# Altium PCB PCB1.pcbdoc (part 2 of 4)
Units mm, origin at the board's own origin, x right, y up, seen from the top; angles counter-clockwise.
Board outline 94.87 x 122.94 mm, 4 copper layers (Top Layer, Inner1, Inner2, Bottom Layer); 129 components, 127 nets, 713 pads, 345 vias.
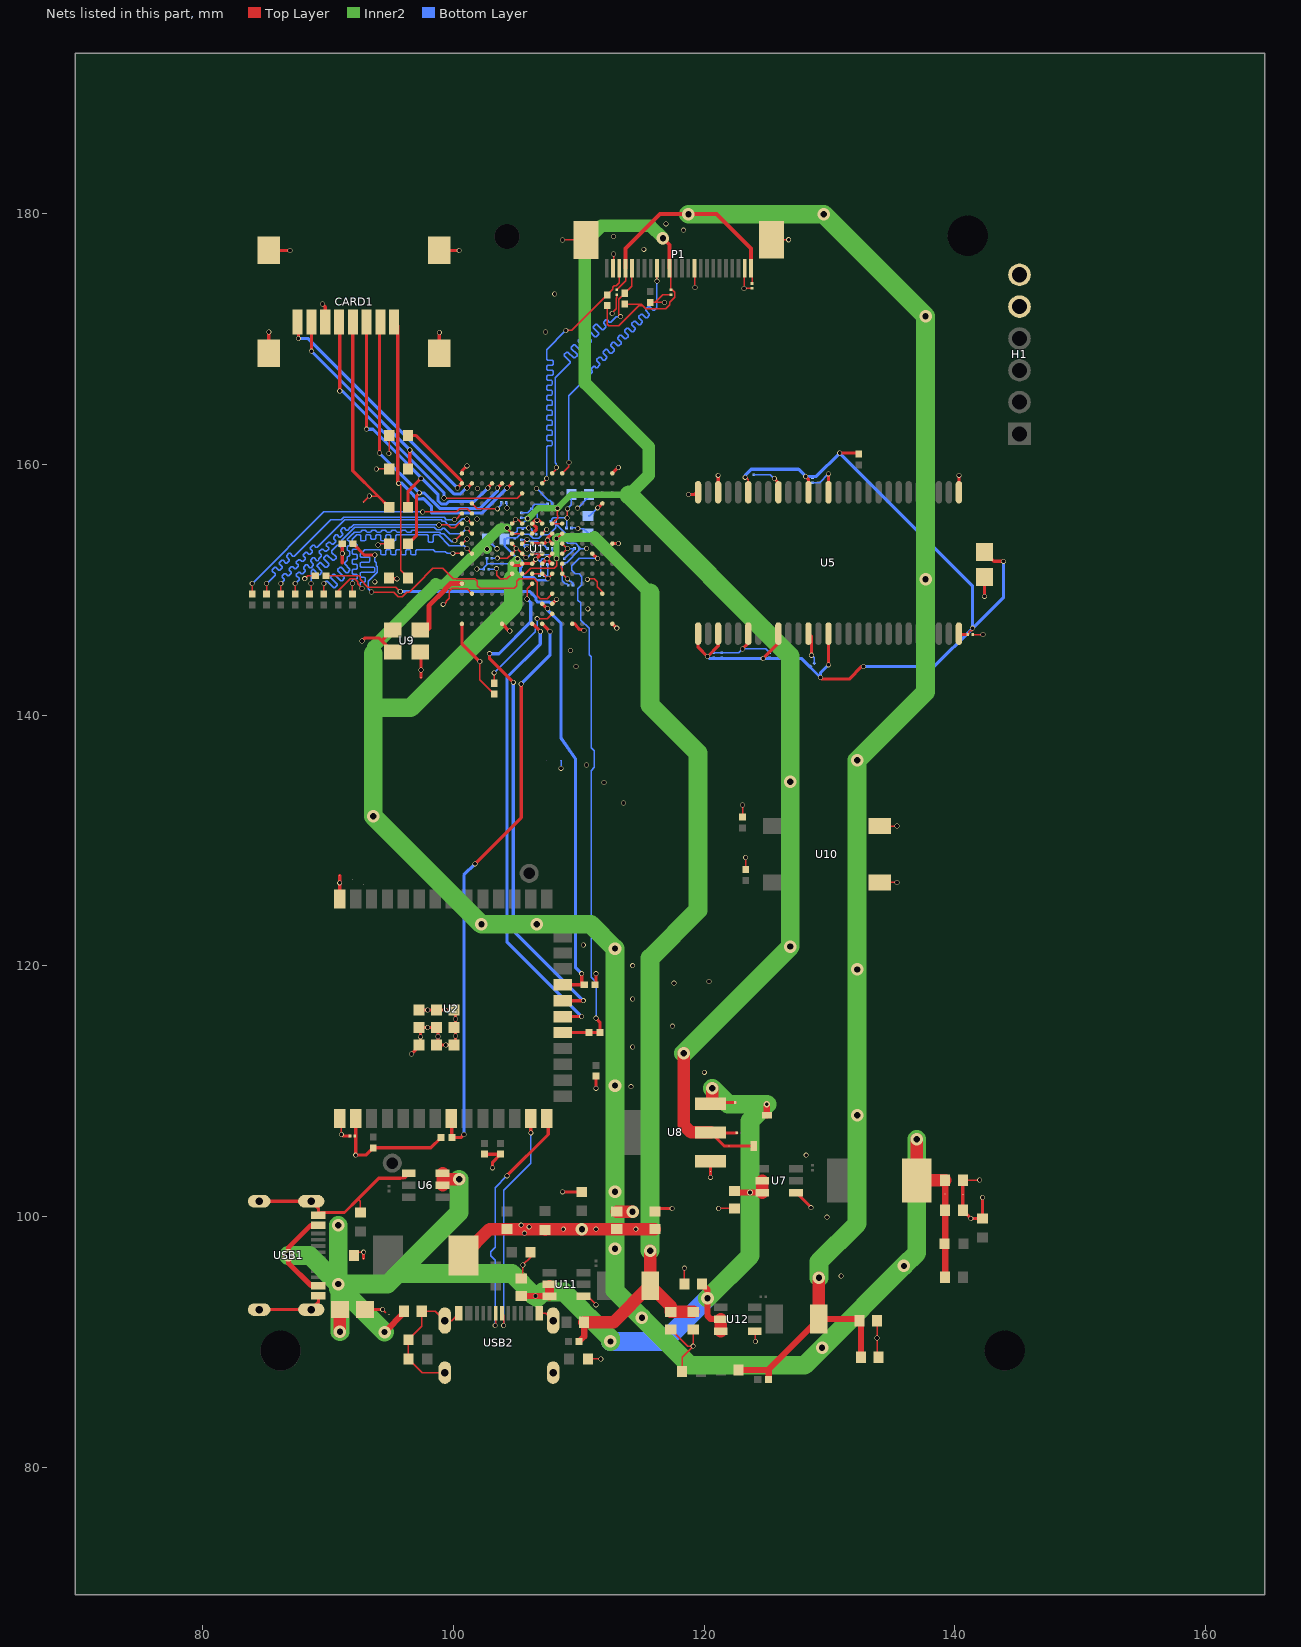
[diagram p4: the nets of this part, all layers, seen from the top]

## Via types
v1: diameter 0.4, hole 0.3, Top Layer to Bottom Layer, 308 vias
v2: diameter 1, hole 0.5, Top Layer to Bottom Layer, 35 vias
v3: diameter 0.5, hole 0.3, Top Layer to Bottom Layer, 2 vias

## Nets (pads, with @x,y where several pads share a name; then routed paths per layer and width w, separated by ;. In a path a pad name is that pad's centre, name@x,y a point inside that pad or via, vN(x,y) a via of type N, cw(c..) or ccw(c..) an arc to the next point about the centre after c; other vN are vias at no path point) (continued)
$2N5507: R23.2 U1.P10 | length 20.1
  Top Layer w0.1: R23.2@89.841,151.13 92.456,151.13 92.562,151.024 92.562,150.836 93.178,150.22 95.398,150.22 v1(95.758,149.86)
  Top Layer w0.254: U1.P10@107.88,148.889 108.204,149.213 v1@108.204,149.225
  Bottom Layer w0.254: v1(95.758,149.86) 106.11,149.86 106.589,149.381 106.589,149.159 106.73,149.018 107.676,149.018 107.776,148.918 107.897,148.918 v1(108.225,149.246)
$2N5509: R24.2 U1.N10 | length 23.9
  Top Layer w0.1: v1(93.472,149.818) 95.231,149.818 95.591,149.458 95.925,149.458 96.285,149.818 96.478,149.818 97.722,151.062 97.722,151.067 98.358,151.703 99.151,151.703 99.983,150.871 101.694,150.871 101.898,150.667 101.898,150.331 102.122,150.107 104.038,150.107 104.045,150.114 104.515,150.114 104.522,150.107 104.838,150.107 105.062,150.331 105.062,150.689 105.244,150.871 106.438,150.871 106.698,150.611 106.698,149.531 106.922,149.307 107.498,149.307 U1.N10@107.88,149.689
  Top Layer w0.254: R24.2@92,153.67 92.889,152.781 v1(93.726,152.781)
  Bottom Layer w0.1: v1(93.472,149.818) 93.218,150.072 93.218,150.697 93.926,151.405 93.926,151.829 93.853,151.902 93.853,152.146 93.726,152.273 v1(93.726,152.781)
$2N5511: R25.2 U1.R10 | length 7.9
  Top Layer w0.1: R25.2@103.251,142.546 v1(103.251,143.383) ; v1(106.68,147.701) 107.492,147.701 U1.R10@107.88,148.089
  Bottom Layer w0.1: v1(103.251,143.383) 106.532,146.664 106.532,146.852 106.68,147 v1(106.68,147.701)
+1V1: C25.2 C27.2 C28.2 C41.1 C42.1 C43.1 C44.1 C49.1 C53.1 C54.1 C61.1 L2.2 pad.55@139.233,101.796 R15.2 U1.G6 U1.G7 U1.L8 U1.L9 U1.L10 | length 172.4
  Top Layer w0.1: v1@104.267,154.94 104.267,154.902 U1.G6@104.68,154.489 U1.G7@105.48,154.489 ; U1.L8@106.28,151.289 U1.L9@107.08,151.289 107.146,151.289 v1(107.539,150.897) 107.88,151.238 U1.L10@107.88,151.289
  Top Layer w0.5: C25.2@139.233,95.162 C28.2@139.233,100.496 pad.55@139.233,101.796 C27.2@139.233,102.909
  Top Layer w1: v2(136.969,106.172) L2.2@136.969,102.864 137.014,102.909 C27.2@139.233,102.909
  Inner2 w0.7: 98.601,150.439 98.614,150.426 ; 103.835,154.932 v1(104.275,154.932)
  Inner2 w0.8: 98.601,150.439 99.936,150.439 ; 99.418,150.613 101.342,152.537 101.403,152.537 101.844,152.978 101.844,153.039 102.371,153.567 ; 99.949,150.426 99.936,150.439 ; v1(102.689,153.249) 102.371,153.567 ; 103.835,154.932 103.813,154.909 103.714,154.909 102.371,153.567 ; v1@105.039,152.302 104.728,151.99 104.728,150.859 104.308,150.439 99.936,150.439
  Inner2 w1: 93.612,145.444 96.696,148.528 96.696,148.534 98.601,150.439
  Inner2 w1.5: 93.609,144.917 93.609,140.564 ; 104.728,150.859 104.775,150.812 104.775,148.785 96.579,140.589 93.634,140.589 93.609,140.564 ; v2(136.969,106.172) 136.969,97.091 v2(135.94,96.062) v2(129.41,89.532) 128.016,88.138 118.841,88.138 v2(115.042,91.937) 112.89,94.089 v2(112.89,97.437) v2(112.89,101.976) v2(112.89,110.453) v2(112.89,121.382) 110.955,123.317 v2(106.641,123.317) v2(102.235,123.317) v2(93.609,131.943) 93.609,140.564
  Bottom Layer w0.1: C61.1@104.205,154.051 104.309,154.155 105.057,154.155 105.33,154.427 106.05,154.427 106.357,154.12 106.801,154.12 107.09,154.411 107.609,154.411 108.145,154.948 108.145,155.194 ; C53.1@107.256,151.13 107.442,151.13 107.51,151.062 C49.1@107.51,152.019 ; C43.1@108.145,155.448 108.145,155.194 ; C44.1@109.161,154.178 109.161,154.289 108.256,155.194 108.145,155.194
  Bottom Layer w0.2: C61.1@104.078,154.051 104.078,153.518 v1(105.117,152.479) 105.245,152.479 105.339,152.385 105.339,152.381 105.445,152.275 105.445,151.859 C54.1@105.351,151.765 105.351,151.316 105.664,151.003 106.422,151.003 106.676,150.749 107.525,150.749 v1@107.539,150.762
+1V8: C29.1 C32.2 C35.1 C62.1 C63.1 P1.11 pad.55@121.997,105.627 R38.2 R39.2 U1.F10 U1.F11 U8.2 | length 124.4
  Top Layer w0.1: v1(108.312,156.504) 108.312,156.262 108.298,156.247 108.298,155.931 108.312,155.917 108.312,155.721 U1.F10@107.88,155.289 U1.F11@108.68,155.289 ; R38.2@112.268,172.668 112.268,172.205 112.264,172.201 112.264,171.2 112.395,171.069 113.177,171.069 114.776,172.668 115.112,172.668 ; R39.2@113.665,172.795 114.985,172.795 115.112,172.668 ; P1.11@117.237,175.655 117.336,175.557 117.336,174.458 117.348,174.446 C35.1@117.348,173.931 ; 117.459,173.931 117.66,173.73 117.66,173.352 117.242,172.934 117.242,172.756 116.924,172.437 115.343,172.437 115.112,172.668
  Top Layer w0.254: C29.1@122.614,106.68 120.546,106.68 121.599,105.627 pad.55@121.997,105.627 C32.2@123.952,105.627
  Top Layer w0.3: v2(116.713,178.054) 117.237,177.53 P1.11@117.237,175.655
  Top Layer w1: v2(118.364,113.03) 118.364,107.315 118.97,106.709 U8.2@120.517,106.709
  Inner2 w0.5: v1(105.928,155.689) 105.965,155.689 106.781,156.504 v1(108.312,156.504) 108.491,156.683 108.491,156.713 109.353,157.575 114.014,157.575
  Inner2 w1: 114.014,157.575 115.57,159.131 115.57,161.417 110.49,166.497 110.49,177.71 111.813,179.033 115.734,179.033 v2(116.713,178.054)
  Inner2 w1.5: 114.014,157.575 126.873,144.716 v2(126.873,134.685) v2(126.873,121.539) v2(118.364,113.03)
  Bottom Layer w0.1: C63.1@105.41,155.761 105.856,155.761 v1(105.928,155.689) 105.537,155.298 C62.1@105.537,155.262
+2V5: C65.2 C67.2 C68.2 L3.2 R41.2 U1.G11 U1.L7 | length 86.3
  Top Layer w0.1: U1.L7@105.48,151.289 105.74,151.289 106.158,151.707 108.038,151.707 108.262,151.931 108.262,152.247 108.232,152.277 v1(108.232,152.489) ; v1(108.232,154.089) 108.632,154.489 U1.G11@108.68,154.489
  Top Layer w0.5: R41.2@110.034,90.043 110.428,90.437 C65.2@110.428,91.567
  Top Layer w1: C65.2@110.428,91.567 112.773,91.567 L3.2@115.694,94.488 ; v2(115.694,97.282) L3.2@115.694,94.488 ; C67.2@119.126,92.394 C68.2@117.348,92.394 117.348,92.834 L3.2@115.694,94.488
  Inner2 w0.5: v1(108.232,152.489) v1(108.232,154.089)
  Inner2 w0.7: v1(108.232,154.089) 108.321,154.178 111.252,154.178
  Inner2 w1: 111.252,154.178 115.694,149.736
  Inner2 w1.5: v2(115.694,97.282) 115.694,120.619 119.507,124.432 119.507,136.989 115.694,140.802 115.694,149.736
+2V8: C34.1 C70.2 C72.2 C73.2 C74.1 L4.2 P1.4 P1.24 R47.2 | length 139.5
  Top Layer w0.1: C34.1@113.03,173.931 113.738,174.639 P1.4@113.738,175.655 ; P1.24@123.739,175.652 123.825,175.566 C74.1@123.825,174.439
  Top Layer w0.3: P1.4@113.738,175.655 113.738,177.23 116.488,179.98 120.986,179.98 123.739,177.227 P1.24@123.739,175.652
  Top Layer w0.5: C70.2@122.747,87.757 125.092,87.757 ; R47.2@125.147,86.995 125.147,87.702 125.092,87.757 ; C73.2@132.396,91.694 132.269,91.821 L4.2@129.156,91.821 125.092,87.757 ; C72.2@132.523,88.773 C73.2@132.523,91.567
  Top Layer w1: L4.2@129.159,91.824 v2(129.159,95.123)
  Inner2 w1.5: v2(118.745,179.959) v2(129.54,179.959) v2(137.668,171.831) v2(137.668,150.833) 137.668,141.859 v2(132.207,136.398) v2(132.207,119.716) v2(132.207,108.091) 132.207,99.441 129.159,96.393 v2(129.159,95.123)
+3V3: C8.1 C10.1 C11.1 C12.1 C13.1 C14.1 C15.2 C16.2 C17.2 C19.2 C22.2 C23.2 C37.1 C39.1 C40.1 C45.1 C46.1 C47.1 C48.1 C50.1 C51.1 C52.1 C55.1 C56.1 C57.1 C58.1 C59.1 CARD1.4 H1.5 L1.2 pad.55@92.806,156.993 R1.2 R3.1 R4.1 R5.2 R7.2 R11.2 R16.2 R17.2 R18.2 R19.2 R20.2 R21.2 R22.2 R23.1 U1.F6 U1.F7 U1.G9 U1.H6 U1.H7 U1.H11 U1.J6 U1.J7 U1.J11 U1.K11 U1.L6 U1.L11 U2.2 U5.1 U5.3 U5.9 U5.14 U5.27 U5.43 U5.49 U9.1 U9.4 | length 156.7
  Top Layer w0.1: v1(88.14,150.887) 88.383,151.13 R23.1@88.975,151.13 ; pad.55@92.806,156.993 v1(93.293,157.48) 93.985,157.48 93.987,157.482 ; v1(93.853,159.639) R18.2@94.878,159.639 ; v1(93.98,153.585) 94.065,153.67 R17.2@94.878,153.67 ; v1@94.878,160.909 R19.2@94.878,162.306 ; v1(103.432,151.689) 103.462,151.659 103.462,151.167 103.753,150.876 104.267,150.876 U1.L6@104.68,151.289 ; v1@103.505,152.527 103.702,152.527 103.722,152.507 104.298,152.507 U1.J6@104.68,152.889 105.008,153.217 v1(105.008,153.288) ; U1.H6@104.68,153.689 105.008,153.361 v1(105.008,153.288) ; U1.F6@104.68,155.289 104.948,155.557 v1(104.948,155.607) 105.162,155.607 U1.F7@105.48,155.289 ; U1.H7@105.48,153.689 105.528,153.689 v1(105.864,154.025) ; v1@105.791,152.527 105.791,152.578 U1.J7@105.48,152.889 105.081,153.288 v1(105.008,153.288) ; U1.G9@107.08,154.489 107.404,154.813 v1(107.442,154.813) ; U1.K11@108.68,152.089 108.68,151.962 108.585,151.867 108.585,151.765 108.68,151.67 U1.L11@108.68,151.289 v1(109.093,150.876) ; U1.J11@108.68,152.889 109.08,153.289 v1(109.093,153.289) 108.693,153.689 U1.H11@108.68,153.689 ; v1(123.277,158.977) 123.344,158.977 123.521,158.8 U5.49@123.521,157.788 ; C14.1@141.029,146.431 141.112,146.514 141.112,146.625 141.23,146.743 141.341,146.743 141.419,146.821 v1(141.419,146.939)
  Top Layer w0.254: CARD1.4@91.975,171.374 91.975,159.494 93.987,157.482 R20.2@94.878,156.591 ; U2.2@92.324,107.836 92.202,107.714 v1(92.202,104.902) 93.016,104.902 R7.2@93.599,105.485 98.194,105.485 R5.2@99.008,106.299 ; v1(92.71,145.923) 92.931,146.144 94.07,146.144 94.291,145.923 ; R16.2@94.874,150.952 94.949,150.876 v1(95.504,150.876) ; U9.1@95.166,145.048 94.291,145.923 ; U9.4@95.166,146.798 94.291,145.923 ; R21.2@102.489,104.977 R22.2@103.759,104.977 103.124,104.342 v1(103.124,103.886) ; R3.1@111.304,118.491 111.379,118.566 v1(111.379,119.38) ; v1(111.379,110.236) R4.1@111.379,111.2 ; U5.1@119.521,146.631 119.521,145.422 v1(120.269,144.674) 121.121,145.526 U5.3@121.121,146.504 ; v1(124.714,144.526) 125.921,145.733 U5.9@125.921,146.504 ; v1(128.103,159.044) 128.321,158.826 U5.43@128.321,157.788 ; v1(129.286,143.002) 129.413,142.875 131.572,142.875 132.588,143.891 v1(132.715,143.891) ; v1(129.921,144.018) U5.14@129.921,146.504 ; v1(130.81,160.909) 132.259,160.909 R1.2@132.334,160.834 ; U5.27@140.321,146.504 140.394,146.431 C14.1@141.029,146.431 ; C8.1@142.367,153.019 143.113,152.273 v1(143.891,152.273)
  Top Layer w1: L1.2@100.79,96.901 102.884,98.995 C19.2@104.267,98.995 107.262,98.995 R11.2@107.315,98.942 107.368,98.995 v1(108.764,98.995) v2(110.25,98.995) v1(111.378,98.995) C23.2@113.03,98.995 v1(114.549,98.995) C22.2@116.078,98.995
  Bottom Layer w0.1: C51.1@102.811,151.638 103.381,151.638 v1(103.432,151.689) ; C56.1@103.065,152.527 103.489,152.527 v1(103.497,152.519) ; C37.1@104.208,156.972 104.267,156.913 v1(104.267,156.524) ; C45.1@105.41,153.992 105.831,153.992 v1(105.864,154.025) 106.034,153.855 106.674,153.855 106.792,153.737 106.792,153.626 C46.1@106.875,153.543 107.247,153.543 C47.1@107.501,153.289 ; v1(105.791,152.568) 105.891,152.568 C57.1@106.231,152.908 ; C50.1@106.621,156.464 107.621,156.464 107.808,156.651 107.808,156.762 C39.1@107.891,156.845 107.891,156.956 107.69,157.157 107.564,157.157 v1(106.632,158.089) ; C52.1@108.839,152.468 C55.1@109.66,153.289 v1(109.093,153.289) ; v1(109.093,150.876) 109.289,150.68 109.341,150.68 109.542,150.479 C48.1@109.542,150.368 ; C40.1@109.415,154.94 109.877,154.94 v1(109.926,154.89) 110.348,154.89 C59.1@110.744,154.494 ; v1(109.904,156.512) 110.809,157.417 C58.1@110.809,157.607
  Bottom Layer w0.254: v1(120.269,144.674) 120.417,144.526 v1(124.714,144.526) 127.762,144.526 v1(129.286,143.002) 129.286,143.383 v1(129.921,144.018) ; v1(123.277,158.977) 123.277,159.125 123.765,159.612 127.535,159.612 v1(128.103,159.044) 128.945,159.044 v1(130.81,160.909) 141.419,150.3 v1(141.419,146.939) ; v1(132.715,143.891) 138.371,143.891 v1(141.419,146.939) ; v1(143.891,152.273) 143.891,149.411 v1(141.419,146.939)
  other v1: 105.664,98.679 106.045,99.187 105.41,99.314 93.726,150.636 94.844,160.876
+5V: C20.2 C26.2 C30.1 C31.2 C33.2 C66.2 C71.2 U6.2 U6.3 U7.2 U7.3 U8.3 U11.2 U11.3 U12.2 U12.3 USB1.A4B9 USB1.B4A9 | length 113.2
  Top Layer w0.254: U8.3@120.904,109.093 C30.1@122.487,109.093
  Top Layer w0.4: USB1.B4A9@89.23,94.501 88.633,94.501 86.83,96.304 86.83,97.508 88.623,99.301 USB1.A4B9@89.23,99.301
  Top Layer w0.5: v2(94.507,90.786) 96.074,92.353 C20.2@96.074,92.456 ; C66.2@105.41,93.661 v1(106.553,93.661) 107.645,93.661 U11.3@107.669,93.637 ; C71.2@119.826,94.615 120.269,94.172 v2(120.269,93.492) 120.269,92.075 120.523,91.821 U12.2@121.332,91.821 ; C26.2@122.428,102.046 122.554,101.92 v3(123.665,101.92) U7.3@124.634,101.92 ; C31.2@125.005,108.077 v3(125.005,108.966)
  Top Layer w0.7: U11.3@107.669,93.637 U11.2@107.669,94.587
  Top Layer w1: v2(90.948,90.805) C33.2@90.948,92.583 ; U6.2@99.14,102.491 99.14,102.97 ; U6.3@99.14,103.439 99.14,102.97 ; v2(100.457,102.97) 99.14,102.97 ; U8.3@120.517,109.009 120.65,109.142 v2(120.65,110.236) ; U12.3@121.332,90.871 U12.2@121.332,91.819 ; U7.3@124.634,101.92 U7.2@124.634,102.868
  Inner2 w1.5: v2(86.816,96.901) 88.519,96.901 v2(90.805,94.615) ; v2(90.805,99.301) v2(90.805,94.615) ; v2(90.948,90.805) 90.948,94.091 v2@90.805,94.234 ; v2(94.507,90.786) 91.059,94.234 v2@90.805,94.234 ; v2(100.457,102.97) 100.457,100.33 95.59,95.463 ; v1(106.553,93.661) 106.457,93.661 104.655,95.463 95.59,95.463 ; v1@106.68,93.534 107.126,93.98 108.839,93.98 110.277,92.542 110.277,92.508 110.923,91.862 110.957,91.862 112.522,90.297 v2(112.522,90.043) ; v2(120.269,93.492) 123.665,96.888 v3(123.665,101.92) 123.665,107.626 v3(125.005,108.966) 121.92,108.966 v2(120.65,110.236) ; v2@90.805,94.234 v2(90.805,94.615) ; v2(90.805,94.615) 94.742,94.615 95.59,95.463
  Bottom Layer w1.5: v2(112.522,90.043) 116.82,90.043 v2(120.269,93.492)
CCLK: R6.1 R6.2 U1.J14 U2.19 | length 44.6
  Top Layer w0.254: U2.19@108.844,114.681 R6.1@110.819,114.681 R6.2@111.685,114.681 111.685,115.518 v1(111.379,115.824) ; U1.J14@111.08,152.889 111.463,152.506 v1(111.506,152.506)
  Bottom Layer w0.1: v1(111.379,115.824) 111.379,118.703 110.977,119.105 110.977,135.577 111.252,135.852 111.252,137.16 110.998,137.414 110.977,137.414 110.977,144.674 110.825,144.826 110.825,146.928 110.167,147.586 110.167,148.951 109.938,149.18 109.938,150.07 110.257,150.389 110.257,151.043 110.022,151.278 109.736,151.278 109.451,151.562 109.451,151.93 110.027,152.506 v1(111.506,152.506)
CRYSTAL: U1.M1 U9.3 | length 5.9
  Top Layer w0.4: U9.3@97.366,146.798 97.874,146.798 98.044,146.968 98.044,148.717 99.324,149.997 99.324,150.044 99.765,150.485 99.812,150.485 99.816,150.489 U1.M1@100.68,150.489
D0: R26.1 U1.E2 | length 21
  Top Layer w0.1: R26.1@83.947,149.658 v1(83.947,150.495) ; v1@97.536,156.21 100.261,156.21 100.522,156.471 101.098,156.471 U1.E2@101.48,156.089
  Bottom Layer w0.1: v1(83.947,150.495) 89.662,156.21 v1(97.546,156.21)
D1: R27.1 U1.E1 | length 21.1
  Top Layer w0.1: R27.1@85.09,149.658 v1(85.09,150.495) ; v1(100.076,155.604) 100.195,155.604 U1.E1@100.68,156.089
  Bottom Layer w0.1: v1(85.09,150.495) 85.775,151.18 85.775,151.28 85.558,151.498 85.558,151.598 85.74,151.78 85.84,151.78 86.058,151.563 86.158,151.563 86.341,151.746 86.341,151.846 86.123,152.063 86.123,152.163 86.306,152.346 86.406,152.346 86.624,152.129 86.724,152.129 86.906,152.311 86.906,152.411 86.689,152.629 86.689,152.729 86.872,152.912 86.972,152.912 87.189,152.694 87.289,152.694 90.199,155.604 91.059,155.604 91.237,155.782 99.269,155.782 99.447,155.604 v1(100.076,155.604)
D2: R28.1 U1.F2 | length 21.5
  Top Layer w0.1: R28.1@86.233,149.658 v1(86.233,150.495) ; v1(101.089,155.659) 101.11,155.659 U1.F2@101.48,155.289
  Bottom Layer w0.1: v1(86.233,150.495) 86.487,150.749 86.487,150.849 86.333,151.003 86.333,151.103 86.516,151.286 86.616,151.286 86.77,151.132 86.87,151.132 87.053,151.315 87.053,151.415 86.899,151.569 86.899,151.669 87.082,151.852 87.182,151.852 87.336,151.698 87.436,151.698 87.618,151.88 87.618,151.98 87.464,152.134 87.464,152.234 87.647,152.417 87.747,152.417 87.901,152.263 88.001,152.263 88.184,152.446 88.184,152.546 88.03,152.7 88.03,152.8 88.213,152.983 88.313,152.983 88.467,152.829 88.567,152.829 88.75,153.012 88.75,153.112 88.596,153.266 88.596,153.366 88.779,153.549 88.879,153.549 89.033,153.395 89.133,153.395 91.32,155.582 99.017,155.582 99.127,155.473 99.295,155.473 99.566,155.202 100.243,155.202 100.699,155.659 v1(101.089,155.659)
D3: R29.1 U1.F1 | length 20.7
  Top Layer w0.1: R29.1@87.376,149.658 v1(87.376,150.495) ; v1(98.851,155.18) 99.55,155.18 99.782,154.948 100.116,154.948 100.474,155.306 100.663,155.306 U1.F1@100.68,155.289
  Bottom Layer w0.1: v1(87.376,150.495) 87.695,150.814 87.695,150.914 87.478,151.132 87.478,151.232 87.661,151.415 87.761,151.415 87.88,151.295 87.98,151.295 88.163,151.478 88.163,151.578 88.043,151.697 88.043,151.797 88.226,151.98 88.326,151.98 88.544,151.763 88.644,151.763 88.827,151.946 88.827,152.046 88.609,152.263 88.609,152.363 88.792,152.546 88.892,152.546 89.11,152.329 89.21,152.329 89.262,152.381 89.262,152.477 89.474,152.69 89.474,152.79 89.305,152.959 89.305,153.059 89.488,153.242 89.588,153.242 89.757,153.072 89.857,153.072 90.04,153.255 90.04,153.355 89.871,153.525 89.871,153.625 90.053,153.807 90.153,153.807 90.323,153.638 90.423,153.638 90.606,153.821 90.606,153.921 90.436,154.09 90.436,154.19 90.619,154.373 90.719,154.373 90.888,154.204 90.988,154.204 91.171,154.387 91.171,154.487 91.002,154.656 91.002,154.756 91.185,154.939 91.285,154.939 91.454,154.769 91.554,154.769 91.763,154.978 91.859,154.978 92.061,155.18 v1(98.851,155.18)
D4: R30.1 U1.G2 | length 21.3
  Top Layer w0.1: R30.1@88.519,149.658 88.646,149.785 v1(88.646,150.495) ; v1(101.074,154.892) 101.077,154.892 U1.G2@101.48,154.489
  Bottom Layer w0.1: v1(88.646,150.495) 88.646,151.482 88.792,151.628 88.81,151.628 89.222,151.216 89.322,151.216 89.505,151.399 89.505,151.499 89.093,151.911 89.093,151.929 89.358,152.194 89.376,152.194 89.788,151.782 89.888,151.782 90.071,151.965 90.071,152.065 89.659,152.477 89.659,152.577 89.842,152.76 89.942,152.76 90.354,152.348 90.454,152.348 90.636,152.531 90.636,152.631 90.297,152.97 90.297,153.133 90.723,153.559 90.823,153.559 91.041,153.341 91.141,153.341 91.324,153.523 91.324,153.623 91.106,153.842 91.106,153.942 92.144,154.98 98.482,154.98 98.684,154.778 99.017,154.778 99.144,154.905 99.253,154.905 99.705,154.453 100.634,154.453 v1(101.074,154.892)
D5: R31.1 U1.G1 | length 21
  Top Layer w0.1: R31.1@89.662,149.658 v1(89.662,150.495) ; v1(100.11,153.924) 100.115,153.924 U1.G1@100.68,154.489
  Bottom Layer w0.1: v1(89.662,150.495) 89.841,150.674 89.941,150.674 90.45,150.165 90.55,150.165 90.733,150.348 90.733,150.448 90.224,150.957 90.224,151.057 90.406,151.239 90.506,151.239 91.016,150.73 91.116,150.73 91.298,150.913 91.298,151.013 90.789,151.522 90.789,151.622 90.953,151.786 91.053,151.786 91.465,151.374 91.565,151.374 91.748,151.556 91.748,151.656 91.336,152.069 91.336,152.169 91.536,152.369 91.536,152.627 91.607,152.697 91.648,152.697 91.719,152.768 91.719,153.027 91.648,153.097 91.607,153.097 91.536,153.168 91.536,153.427 91.607,153.497 91.648,153.497 91.719,153.568 91.719,153.827 91.648,153.897 91.607,153.897 91.536,153.968 91.536,154.042 91.982,154.488 92.004,154.488 92.094,154.578 92.579,154.578 92.65,154.649 92.65,154.68 92.721,154.751 92.979,154.751 93.05,154.68 93.05,154.649 93.121,154.578 93.379,154.578 93.45,154.649 93.45,154.68 93.521,154.751 93.779,154.751 93.85,154.68 93.85,154.649 93.921,154.578 94.179,154.578 94.25,154.649 94.25,154.68 94.321,154.751 94.579,154.751 94.65,154.68 94.65,154.649 94.721,154.578 94.979,154.578 95.05,154.649 95.05,154.68 95.121,154.751 95.379,154.751 95.45,154.68 95.45,154.649 95.521,154.578 95.779,154.578 95.85,154.649 95.85,154.68 95.921,154.751 96.179,154.751 96.25,154.68 96.25,154.649 96.321,154.578 96.579,154.578 96.65,154.649 96.65,154.68 96.721,154.751 96.979,154.751 97.05,154.68 97.05,154.649 97.121,154.578 98.905,154.578 98.995,154.488 99.224,154.488 99.878,153.834 100.02,153.834 v1(100.11,153.924)
D6: R32.1 U1.J1 | length 20.9
  Top Layer w0.1: R32.1@90.805,149.658 90.805,149.921 91.781,150.897 92.115,150.897 92.35,150.662 92.35,150.474 v1(92.71,150.114) ; v1(99.949,152.908) 100.661,152.908 U1.J1@100.68,152.889
  Bottom Layer w0.1: v1(92.71,150.114) 92.562,150.262 92.562,150.546 92.633,150.617 92.897,150.617 92.968,150.687 92.968,150.946 92.897,151.017 92.633,151.017 92.562,151.087 92.562,151.346 92.633,151.417 93.655,151.417 93.726,151.487 93.726,151.746 93.655,151.817 92.633,151.817 92.562,151.887 92.562,152.146 92.633,152.217 93.274,152.217 93.345,152.287 93.345,152.546 93.274,152.617 92.633,152.617 92.562,152.687 92.562,152.821 92.924,153.183 94.142,153.183 94.213,153.112 94.213,152.852 94.283,152.781 94.542,152.781 94.613,152.852 94.613,153.112 94.683,153.183 94.942,153.183 95.013,153.112 95.013,152.852 95.083,152.781 95.342,152.781 95.413,152.852 95.413,153.112 95.483,153.183 95.742,153.183 95.813,153.112 95.813,152.852 95.883,152.781 96.142,152.781 96.213,152.852 96.213,153.112 96.283,153.183 96.542,153.183 96.613,153.112 96.613,152.852 96.683,152.781 96.942,152.781 97.013,152.852 97.013,153.112 97.083,153.183 98.404,153.183 98.531,153.056 99.354,153.056 99.502,152.908 v1(99.949,152.908)
D7: R34.1 U1.J2 | length 21
  Top Layer w0.1: R34.1@91.948,149.658 v1(91.948,150.495) ; v1(101.092,153.289) 101.092,153.277 U1.J2@101.48,152.889
  Bottom Layer w0.1: v1(91.948,150.495) 91.948,150.769 92.019,150.84 92.262,150.84 92.333,150.911 92.333,151.169 92.262,151.24 92.019,151.24 91.948,151.311 91.948,151.569 92.019,151.64 92.262,151.64 92.333,151.711 92.333,151.969 92.262,152.04 92.019,152.04 91.948,152.111 91.948,152.369 92.019,152.44 92.262,152.44 92.333,152.511 92.333,152.769 92.262,152.84 92.019,152.84 91.948,152.911 91.948,153.169 92.019,153.24 92.262,153.24 92.333,153.311 92.333,153.569 92.262,153.64 92.019,153.64 91.948,153.711 91.948,154.051 92.275,154.378 92.524,154.378 92.594,154.307 92.594,153.969 92.665,153.898 92.924,153.898 92.994,153.969 92.994,154.307 93.065,154.378 93.324,154.378 93.394,154.307 93.394,154.11 93.465,154.04 93.724,154.04 93.794,154.11 93.794,154.307 93.865,154.378 94.124,154.378 94.194,154.307 94.194,153.969 94.265,153.898 94.524,153.898 94.594,153.969 94.594,154.307 94.665,154.378 94.924,154.378 94.994,154.307 94.994,153.969 95.065,153.898 95.324,153.898 95.394,153.969 95.394,154.307 95.465,154.378 97.919,154.378 97.989,154.307 97.989,153.868 98.06,153.797 98.319,153.797 98.389,153.868 98.389,154.307 98.46,154.378 98.823,154.378 99.679,153.522 100.859,153.522 v1(101.092,153.289)
DIN: U1.T8 U2.20 | length 36.6
  Top Layer w0.254: U1.T8@106.28,147.289 106.33,147.289 v1(106.934,146.685) ; U2.20@108.844,115.951 v1(110.236,115.951)
  Bottom Layer w0.254: v1(106.934,146.685) 106.934,145.669 104.267,143.002 104.267,121.92 v1(110.236,115.951)
DN: U2.13 USB2.A7 | length 18.5
  Top Layer w0.1: USB2.A7@103.882,92.278 104.013,92.147 v1(104.013,91.313)
  Top Layer w0.254: v1(106.172,106.68) 106.172,107.714 U2.13@106.294,107.836
  Bottom Layer w0.1: v1(104.013,91.313) 104.013,102.108 106.172,104.267 v1(106.172,106.68)
DONE: pad.55@109.22,137.16 R3.2 U1.P9 U2.22 | length 33.3
  Top Layer w0.254: U1.P9@107.08,148.889 107.45,148.519 v1(107.498,148.519) ; U2.22@108.844,118.491 R3.2@110.438,118.491 110.236,118.693 v1(110.236,119.38)
  Bottom Layer w0.254: v1(107.498,148.519) 107.498,148.407 108.585,147.32 108.585,138.176 109.728,136.525 109.728,119.888 v1(110.236,119.38)
DOUT: U1.M8 U2.21 | length 40
  Top Layer w0.1: v1(105.88,149.274) 105.88,150.089 U1.M8@106.28,150.489
  Top Layer w0.254: v1(102.87,144.907) 102.87,144.526 v1(104.775,142.621) ; U2.21@108.844,117.221 v1(110.363,117.221)
  Bottom Layer w0.254: v1(102.87,144.907) 103.632,144.907 106.164,147.439 106.164,148.99 v1(105.88,149.274) ; v1(104.775,142.621) 104.775,122.809 v1(110.363,117.221)
DP: U2.14 USB2.A6 | length 19.5
  Top Layer w0.1: v1@103.382,91.313 USB2.A6@103.382,92.278
  Top Layer w0.254: v1(104.267,103.251) 107.564,106.548 U2.14@107.564,107.836
  Bottom Layer w0.1: v1(103.334,91.313) 103.334,96.503 102.976,96.861 102.976,97.195 103.334,97.553 103.334,102.318 v1(104.267,103.251)
FSCL: P1.5 R39.1 U1.A10 | length 27
  Top Layer w0.1: U1.A10@107.88,159.289 108.204,159.613 v1(108.204,159.766) ; v1(113.327,171.788) 113.193,171.922 113.193,173.162 113.665,173.634 R39.1@113.665,173.661 114.237,174.233 P1.5@114.237,175.655
  Bottom Layer w0.1: v1(108.204,159.766) 108.204,160.052 108.123,160.132 108.123,166.923 109.312,168.112 109.312,168.212 108.84,168.684 108.84,168.784 109.023,168.967 109.123,168.967 109.595,168.495 109.695,168.495 109.878,168.678 109.878,168.778 109.406,169.25 109.406,169.35 109.589,169.533 109.689,169.533 110.161,169.061 110.261,169.061 110.444,169.244 110.444,169.344 109.972,169.816 109.972,169.916 110.155,170.099 110.255,170.099 110.727,169.626 110.827,169.626 111.01,169.809 111.01,169.909 110.587,170.331 110.587,170.431 110.77,170.614 110.87,170.614 111.292,170.192 111.392,170.192 111.575,170.375 111.575,170.475 111.153,170.897 111.153,170.997 111.336,171.18 111.436,171.18 111.858,170.758 111.958,170.758 112.164,170.963 112.164,171.063 111.974,171.253 111.974,171.353 112.157,171.536 112.257,171.536 112.447,171.346 112.547,171.346 112.988,171.788 v1(113.327,171.788)
FSDA: P1.3 R38.1 U1.B9 | length 27
  Top Layer w0.1: U1.B9@107.08,158.489 107.442,158.851 v1(107.442,158.877) ; v1(108.966,170.688) 109.422,170.688 R38.1@112.268,173.534 112.718,173.984 112.718,174.12 112.836,174.238 112.972,174.238 113.237,174.503 P1.3@113.237,175.655
  Bottom Layer w0.1: v1(107.442,158.877) 107.442,161.431 107.513,161.502 107.829,161.502 107.9,161.573 107.9,161.831 107.829,161.902 107.513,161.902 107.442,161.973 107.442,162.242 107.513,162.313 107.829,162.313 107.9,162.383 107.9,162.642 107.829,162.713 107.513,162.713 107.442,162.783 107.442,163.042 107.513,163.113 107.829,163.113 107.9,163.183 107.9,163.442 107.829,163.513 107.513,163.513 107.442,163.583 107.442,163.842 107.513,163.913 107.829,163.913 107.9,163.983 107.9,164.242 107.829,164.313 107.513,164.313 107.442,164.383 107.442,164.642 107.513,164.713 107.829,164.713 107.9,164.783 107.9,165.042 107.829,165.113 107.513,165.113 107.442,165.183 107.442,165.442 107.513,165.513 107.829,165.513 107.9,165.583 107.9,165.842 107.829,165.913 107.513,165.913 107.442,165.983 107.442,166.242 107.513,166.313 107.829,166.313 107.9,166.383 107.9,166.642 107.829,166.713 107.513,166.713 107.442,166.783 107.442,167.042 107.513,167.113 107.879,167.113 107.95,167.183 107.95,167.442 107.879,167.513 107.513,167.513 107.442,167.583 107.442,167.842 107.513,167.913 107.879,167.913 107.95,167.983 107.95,168.242 107.879,168.313 107.513,168.313 107.442,168.383 107.442,169.164 v1(108.966,170.688)
GND: C8.2 C10.2 C11.2 C12.2 C13.2 C14.2 C15.1 C16.1 C17.1 C20.1 C22.1 C23.1 C26.1 C27.1 C28.1 C33.1 C34.2 C35.2 C37.2 C39.2 C40.2 C41.2 C42.2 C43.2 C44.2 C45.2 C46.2 C47.2 C48.2 C49.2 C50.2 C51.2 C52.2 C53.2 C54.2 C55.2 C56.2 C57.2 C58.2 C59.2 C61.2 C62.2 C63.2 C66.1 C67.1 C68.1 C71.1 C72.1 C73.1 C74.2 CARD1.6 CARD1.9 CARD1.10 CARD1.11 CARD1.12 H1.6 P1.2 P1.15 P1.23 P1.25 P1.26 pad.55@90.927,127.195 pad.55@92.837,96.647 pad.55@94.869,92.202 pad.55@97.409,143.002 pad.55@108.585,136.398 pad.55@120.517,103.597 pad.55@140.633,101.756 R9.1 R10.1 R12.1 R14.1 R24.1 R25.1 R35.2 R36.2 R37.2 R40.1 R42.2 R43.2 R45.1 R46.1 U1.A1 U1.A16 U1.D2 U1.D15 U1.F8 U1.F9 U1.G8 U1.G10 U1.H1 U1.H8 U1.H9 U1.H10 U1.H16 U1.J8 U1.J9 U1.J10 U1.K6 U1.K7 U1.K8 U1.K9 U1.K10 U1.N2 U1.N15 U1.T1 U1.T5 U1.T12 U1.T16 U2.1 U2.40 U2.41 U5.6 U5.12 U5.28 U5.41 U5.46 U5.52 U5.54 U6.4 U7.4 U8.1 U9.2 U10.2 U10.4 U11.4 U12.4 USB1.1 USB1.2 USB1.3 USB1.4 USB1.A1B12 USB1.B1A12 USB2.1 USB2.2 USB2.3 USB2.4 USB2.A1B12 USB2.B1A12 | length 193.9
  Top Layer w0.1: U2.1@90.927,107.836 91.054,107.709 v1(91.054,106.553) ; R10.1@92.066,96.901 92.32,97.155 v1(92.837,97.155) ; 92.407,101.415 92.583,101.239 R9.1@92.583,100.321 ; v1(94.361,92.583) 94.615,92.329 ; v1(99.187,148.844) 99.261,148.844 99.42,149.003 99.42,149.088 99.674,149.342 99.674,149.9 99.909,150.135 100.436,150.135 100.494,150.077 101.092,150.077 U1.N2@101.48,149.689 ; USB2.3@99.312,87.554 97.494,87.554 R42.2@96.402,88.646 R43.2@96.402,90.17 97.474,91.242 C20.1@97.474,92.456 98.559,92.456 USB2.1@99.312,91.703 99.857,91.703 USB2.A1B12@100.432,92.278 ; 100.838,153.797 101.08,154.039 v1(101.08,154.051) ; U1.D2@101.48,156.889 101.905,156.464 102.115,156.464 102.122,156.471 103.238,156.471 103.245,156.464 v1@103.505,156.464 ; v1(102.108,144.272) 102.108,142.823 R25.1@103.251,141.68 ; C66.1@105.41,95.061 105.537,95.188 v1(105.537,96.139) 106.163,96.765 R45.1@106.163,97.155 ; U1.J8@106.28,152.889 U1.J9@107.023,152.889 ; USB2.B1A12@106.832,92.278 107.377,92.278 USB2.2@107.952,91.703 ; v1(108.712,177.909) P1.26@110.582,177.909 ; v1(109.08,155.737) 109.093,155.75 v1(109.093,156.464) ; U11.4@110.369,93.637 110.706,93.637 v1(111.379,92.964) ; v1(110.68,150.841) 110.819,150.841 110.849,150.871 111.238,150.871 111.462,150.647 111.462,150.258 111.88,149.84 U1.N15@111.88,149.689 ; R40.1@110.735,88.646 v1(111.76,88.646) ; v1(112.666,172.035) 112.666,172.102 112.993,172.429 112.993,173.245 113.03,173.282 C34.2@113.03,173.541 ; P1.2@112.738,175.655 112.776,175.694 v1(112.776,176.784) ; R35.2@115.697,172.922 116.094,172.922 ; v1(116.84,172.922) 116.094,172.922 ; C68.1@117.348,90.994 118.68,89.662 v1(119.126,89.662) ; C35.2@117.348,173.541 116.713,173.541 116.094,172.922 ; R46.1@118.246,87.63 118.246,88.782 v1(119.126,89.662) ; C71.1@118.426,94.615 v1(118.426,95.885) ; C67.1@119.126,90.994 v1(119.126,89.662) ; P1.15@119.234,175.654 119.27,175.617 119.27,174.455 119.253,174.437 v1@119.253,174.117 ; v1(121.158,100.646) C26.1@122.428,100.646 ; R36.2@123.063,131.878 v1(123.063,132.842) ; P1.23@123.239,175.652 123.19,175.603 v1(123.19,174.045) 123.194,174.049 C74.2@123.825,174.049 ; R37.2@123.317,127.687 v1(123.317,128.651) ; U12.4@124.032,90.871 124.079,90.824 v1(124.079,90.043) ; P1.25@125.384,177.916 126.735,177.916 v1(126.746,177.927) ; C73.1@133.796,91.694 v1(133.796,90.323) 133.796,88.9 C72.1@133.923,88.773 ; U10.4@133.994,126.655 v1(135.382,126.655) ; U10.2@133.994,131.155 v1(135.382,131.155) ; C27.1@140.633,102.909 v1(141.986,102.909) ; C14.2@141.419,146.431 v1(142.24,146.431)
  Top Layer w0.254: USB1.4@84.506,92.581 USB1.2@88.655,92.581 89.23,93.156 USB1.B1A12@89.23,93.701 ; USB1.3@84.506,101.221 USB1.1@88.655,101.221 89.23,100.646 USB1.A1B12@89.23,100.101 89.451,100.321 91.313,100.321 92.407,101.415 94.05,103.058 95.764,103.058 95.774,103.068 96.069,103.068 U6.4@96.44,103.439 ; CARD1.10@85.275,168.874 v1(85.275,170.565) ; CARD1.9@85.275,177.074 v1(86.96,177.074) ; v1(89.548,172.801) 89.775,172.574 CARD1.6@89.775,171.374 ; pad.55@90.927,127.195 v1(90.927,126.623) 90.927,125.463 U2.40@91.054,125.336 ; v1(91.054,106.553) 91.181,106.426 C17.1@91.753,106.426 ; 91.134,152.146 v1(91.134,152.902) R24.1@91.134,153.67 ; pad.55@92.837,96.647 v1(92.837,97.155) ; C33.1@92.948,92.583 v1(94.361,92.583) ; v1(96.648,112.96) 97.374,113.686 v1(97.374,114.339) 97.374,115.086 v1(97.95,115.086) 98.774,115.086 v1(98.774,114.364) 98.774,113.686 v1(99.394,113.686) 100.174,113.686 v1(100.174,114.408) v1(100.174,115.77) 100.174,116.486 v1(99.325,116.486) U2.41@98.647,116.486 v1(97.95,116.486) U2.41@97.374,116.486 ; U9.2@97.366,145.048 97.409,145.005 v1(97.409,143.607) pad.55@97.409,143.002 ; CARD1.11@98.875,168.874 v1(98.875,170.523) ; CARD1.12@98.875,177.074 v1(100.457,177.074) ; U1.T1@100.68,147.289 100.68,145.7 v1(102.108,144.272) ; U1.A1@100.68,159.289 100.68,159.481 v1(101.092,159.893) ; U1.T5@103.88,147.289 104.463,146.706 v1(104.5,146.706) ; U1.K6@104.68,152.089 104.821,151.948 105.339,151.948 U1.K7@105.48,152.089 U1.K8@106.28,152.089 106.567,152.376 v1(106.567,152.432) 107.023,152.889 U1.J9@107.08,152.889 ; U1.H8@106.28,153.689 U1.H9@107.08,153.689 107.231,153.689 v1(107.499,153.957) ; U1.G8@106.28,154.489 106.632,154.841 106.632,154.937 U1.F8@106.28,155.289 106.534,155.543 v1(106.671,155.543) 106.826,155.543 U1.F9@107.08,155.289 ; U1.K9@107.08,152.089 107.459,152.468 v1(107.459,152.481) ; U1.K10@107.724,152.117 107.724,152.215 v1(107.459,152.481) ; U1.J10@107.88,152.889 107.867,152.889 v1(107.459,152.481) ; U1.H10@107.88,153.689 107.612,153.957 v1(107.499,153.957) ; U1.G10@107.88,154.489 107.499,154.108 v1(107.499,153.957) ; v1(108.712,101.972) R12.1@110.236,101.972 ; U1.T12@109.48,147.289 109.667,147.289 109.821,147.135 109.821,147.099 110.09,146.83 110.35,146.83 v1(110.423,146.757) ; v1@111.506,156.591 111.582,156.591 U1.D15@111.88,156.889 ; U1.T16@112.68,147.289 v1(113.03,146.939) ; U1.H16@112.68,153.689 v1(113.157,153.691) ; U1.A16@112.68,159.289 v1(113.157,159.766) ; C22.1@116.078,100.395 116.329,100.646 v1(117.449,100.646) ; v1(118.745,157.607) 119.213,157.607 U5.54@119.521,157.915 ; v1(120.517,103.134) pad.55@120.517,103.597 U8.1@120.517,104.409 ; U5.52@121.121,157.915 v1(121.121,159.131) ; v1(123.063,145.288) 123.521,145.746 U5.6@123.521,146.504 ; v1(125.603,158.877) 125.921,158.559 U5.46@125.921,157.788 ; U7.4@127.334,101.92 128.524,100.73 v1(128.524,100.711) ; U5.12@128.321,146.504 128.575,146.25 v1(128.575,144.78) ; U5.41@129.921,157.915 v1(129.921,159.258) ; U5.28@140.321,157.788 140.335,157.802 v1(140.335,159.131) ; C27.1@140.633,102.909 pad.55@140.633,101.756 C28.1@140.633,100.496 v1(141.277,99.852) R14.1@142.219,99.852 v1(142.219,101.512) ; v1(142.367,149.479) C8.2@142.367,151.019
  Top Layer w1: C23.1@113.03,100.395 v2(114.292,100.395)
  Bottom Layer w0.1: v1@101.854,151.638 C51.2@102.421,151.638 102.421,151.749 102.675,152.003 ; C56.2@102.675,152.527 102.675,152.003 ; C61.2@102.678,154.051 102.692,154.051 v1(103.467,153.276) ; v1(103.504,156.465) 103.818,156.779 C37.2@103.818,156.972 ; C41.2@104.902,154.5 105.08,154.678 105.08,154.937 105.472,154.937 C62.2@105.537,154.872 105.602,154.937 v1(106.007,154.937) 106.107,154.937 106.23,154.814 106.23,154.754 106.466,154.518 106.526,154.518 C42.2@106.612,154.432 ; C54.2@104.961,151.765 104.635,152.091 102.763,152.091 102.675,152.003 ; C45.2@105.41,153.602 C45.2@105.519,153.602 ; C63.2@105.41,156.151 105.918,156.151 C50.2@106.231,156.464 ; v1(105.866,153.256) C45.2@105.519,153.602 ; v1(106.567,152.432) 106.706,152.432 106.949,152.19 ; v1(106.671,155.543) 106.671,156.024 106.543,156.152 106.432,156.152 106.314,156.27 106.314,156.381 C50.2@106.231,156.464 ; C53.2@106.866,151.13 106.949,151.213 106.949,151.919 107.049,152.019 C49.2@107.12,152.019 106.949,152.19 ; C39.2@107.501,156.845 106.501,156.845 106.314,156.658 106.314,156.547 C50.2@106.231,156.464 ; C43.2@107.755,155.448 107.838,155.531 107.838,155.642 107.956,155.76 108.334,155.76 108.357,155.737 v1(109.08,155.737) 109.025,155.682 C40.2@109.025,154.94 ; C47.2@107.891,153.289 107.891,152.913 107.791,152.813 ; v1(108.585,135.763) pad.55@108.585,136.398 ; C44.2@108.771,154.178 108.771,154.067 109.137,153.701 109.749,153.701 110.05,153.4 C55.2@110.05,153.289 ; v1(109.093,156.464) 109.409,156.78 C58.2@109.409,157.607 ; C48.2@109.152,150.368 109.046,150.474 108.926,150.474 108.691,150.709 108.691,151.93 C52.2@108.839,152.078 108.922,152.161 109.033,152.161 110.05,153.178 C55.2@110.05,153.289 ; v1@110.617,153.289 C55.2@110.05,153.289 ; C59.2@110.744,155.894 110.857,155.894 v1(111.506,156.544) ; C10.2@120.777,144.975 C11.2@121.412,144.975 122.75,144.975 v1(123.063,145.288) 124.909,145.288 C12.2@125.222,144.975 ; C16.1@123.952,159.19 125.29,159.19 v1(125.603,158.877) ; v1(128.575,144.78) 128.789,144.566 C13.2@128.789,144.156 ; C15.1@128.651,158.555 129.218,158.555 v1(129.921,159.258) ; C45.2@105.519,153.602 106.426,153.602 C46.2@106.485,153.543 106.538,153.49 106.538,152.991 C57.2@106.621,152.908 106.716,152.813 107.791,152.813 ; 106.949,152.19 106.949,152.331 107.099,152.481 v1(107.459,152.481) 107.791,152.813
  other v1: 130.937,95.25 129.794,99.949 128.143,104.902 114.173,110.363 120.015,111.506 114.3,113.538 117.475,115.189 114.3,117.348 117.602,118.618 120.396,118.745 114.3,120.015 110.363,121.666 113.561,132.992 112.014,134.62 110.617,136.017 109.784,143.891 109.347,145.161 110.724,148.485 101.869,151.653 110.632,153.289 101.882,155.659 101.929,158.088 107.336,170.561 108.077,173.609 119.27,174.117 115.189,177.165 112.776,178.181 118.364,178.689 116.967,179.197
HREF: P1.9 U1.A11 | length 27
  Top Layer w0.1: U1.A11@108.68,159.289 109.22,159.829 v1(109.22,160.147) ; v1(116.237,174.625) P1.9@116.237,175.655
  Bottom Layer w0.1: v1(109.22,160.147) 109.22,165.481 111.088,167.349 111.088,167.449 110.998,167.54 110.998,167.64 111.181,167.823 111.281,167.823 111.371,167.732 111.471,167.732 111.682,167.943 111.682,168.043 111.451,168.274 111.451,168.374 111.634,168.557 111.734,168.557 111.965,168.326 112.065,168.326 112.248,168.509 112.248,168.609 111.967,168.89 111.967,168.99 112.15,169.173 112.25,169.173 112.531,168.892 112.631,168.892 112.814,169.075 112.814,169.175 112.533,169.456 112.533,169.556 112.716,169.739 112.816,169.739 113.097,169.458 113.197,169.458 113.379,169.64 113.379,169.74 113.098,170.021 113.098,170.121 113.281,170.304 113.381,170.304 113.662,170.023 113.762,170.023 113.945,170.206 113.945,170.306 113.664,170.587 113.664,170.687 113.847,170.87 113.947,170.87 114.228,170.589 114.328,170.589 114.511,170.772 114.511,170.872 114.23,171.153 114.23,171.253 114.413,171.436 114.513,171.436 114.794,171.155 114.894,171.155 115.077,171.338 115.077,171.438 114.796,171.719 114.796,171.819 114.978,172.001 115.078,172.001 115.359,171.72 115.459,171.72 115.642,171.903 115.642,172.003 115.361,172.284 115.361,172.384 115.544,172.567 115.644,172.567 115.925,172.286 116.025,172.286 116.237,172.498 v1(116.237,174.625)
INITN: pad.55@100.838,127.254 R5.1 U1.T9 U2.8 | length 46.5
  Top Layer w0.254: U2.8@99.944,107.836 99.874,107.766 R5.1@99.874,106.299 100.584,106.299 v1(100.838,106.553) ; v1(101.727,128.143) 105.41,131.826 v1(105.41,142.494) ; U1.T9@107.08,147.289 107.684,146.685 v1(107.696,146.685)
  Bottom Layer w0.254: v1(100.838,106.553) pad.55@100.838,127.254 v1(101.727,128.143) ; v1(105.41,142.494) 107.696,144.78 v1(107.696,146.685)
M_CLK: CARD1.5 U1.C7 | length 24
  Top Layer w0.1: v1(99.242,157.325) 99.259,157.307 105.098,157.307 U1.C7@105.48,157.689
  Top Layer w0.254: CARD1.5@90.875,171.374 90.932,171.317 v1(90.932,165.862)
  Bottom Layer w0.254: v1(90.932,165.862) 91.144,165.862 99.242,157.764 v1(99.242,157.325)
M_CMD: CARD1.3 R20.1 U1.B4 | length 24.7
  Top Layer w0.254: v1(93.075,162.814) CARD1.3@93.075,171.374 ; R20.1@96.384,156.591 96.384,157.852 v1(97.409,158.877) ; v1(102.743,158.115) 102.743,158.152 U1.B4@103.08,158.489
  Bottom Layer w0.254: v1(93.075,162.814) 93.583,162.814 98.763,157.634 98.763,157.126 99.043,156.846 99.44,156.846 99.639,157.045 101.673,157.045 v1(102.743,158.115)
M_D0: CARD1.7 R18.1 U1.B2 | length 21.8
  Top Layer w0.254: v1(88.675,169.037) CARD1.7@88.675,171.374 ; R18.1@96.384,159.639 96.52,159.775 v1(96.52,161.163) ; v1(101.092,158.115) 101.106,158.115 U1.B2@101.48,158.489
  Bottom Layer w0.254: v1(88.675,169.037) 100.076,157.636 100.528,157.636 101.007,158.115 v1(101.092,158.115)
M_D1: CARD1.8 R19.1 U1.B1 | length 25.5
  Top Layer w0.254: CARD1.8@87.575,171.374 87.63,171.319 v1(87.63,170.053) ; R19.1@96.384,162.306 97.019,162.306 100.221,159.104 100.221,159.099 100.49,158.83 100.495,158.83 100.647,158.678 U1.B1@100.647,158.456 ; v1(100.33,158.115) 100.33,158.139 U1.B1@100.647,158.456 ; U1.B1@100.68,158.489 U1.B1@100.647,158.456
  Bottom Layer w0.254: v1(87.63,170.053) 88.392,170.053 v1(100.33,158.115)
M_D2: CARD1.1 R16.1 U1.B6 | length 32.2
  Top Layer w0.1: v1(95.631,158.496) 95.779,158.348 95.779,151.553 R16.1@96.38,150.952
  Top Layer w0.254: CARD1.1@95.275,171.374 95.56,171.089 95.56,158.567 v1(95.631,158.496) ; v1(104.267,158.115) 104.306,158.115 U1.B6@104.68,158.489
  Bottom Layer w0.254: v1(95.631,158.496) 95.885,158.496 96.803,157.578 96.803,157.536 97.084,157.255 97.48,157.255 97.494,157.269 97.619,157.269 98.256,156.632 98.256,156.138 102.29,156.138 v1(104.267,158.115)
M_D3: CARD1.2 R17.1 U1.B5 | length 27.5
  Top Layer w0.254: v1(94.107,160.909) 94.107,171.306 CARD1.2@94.175,171.374 ; R17.1@96.384,153.67 97.067,154.352 97.067,157.519 v1(97.282,157.734) ; v1(103.505,158.115) U1.B5@103.88,158.489
  Bottom Layer w0.254: v1(94.107,160.909) v1(97.282,157.734) 97.654,157.734 98.897,156.492 102.143,156.492 103.505,157.854 v1(103.505,158.115)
